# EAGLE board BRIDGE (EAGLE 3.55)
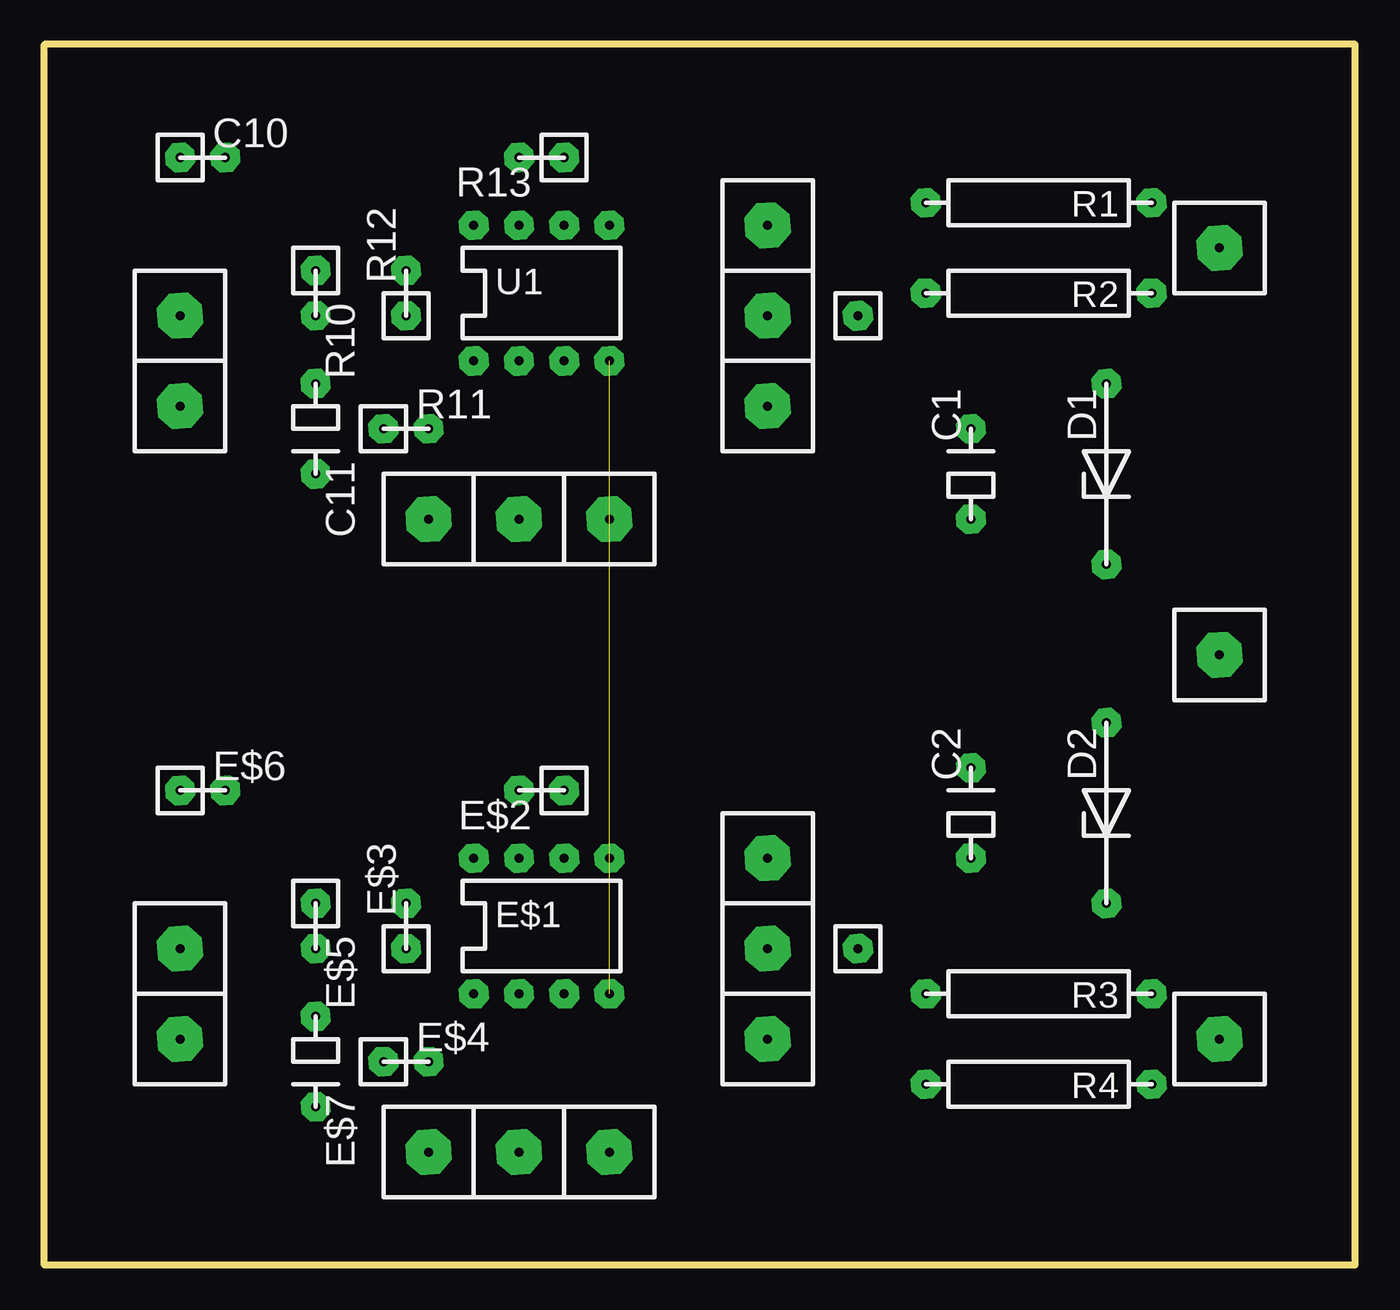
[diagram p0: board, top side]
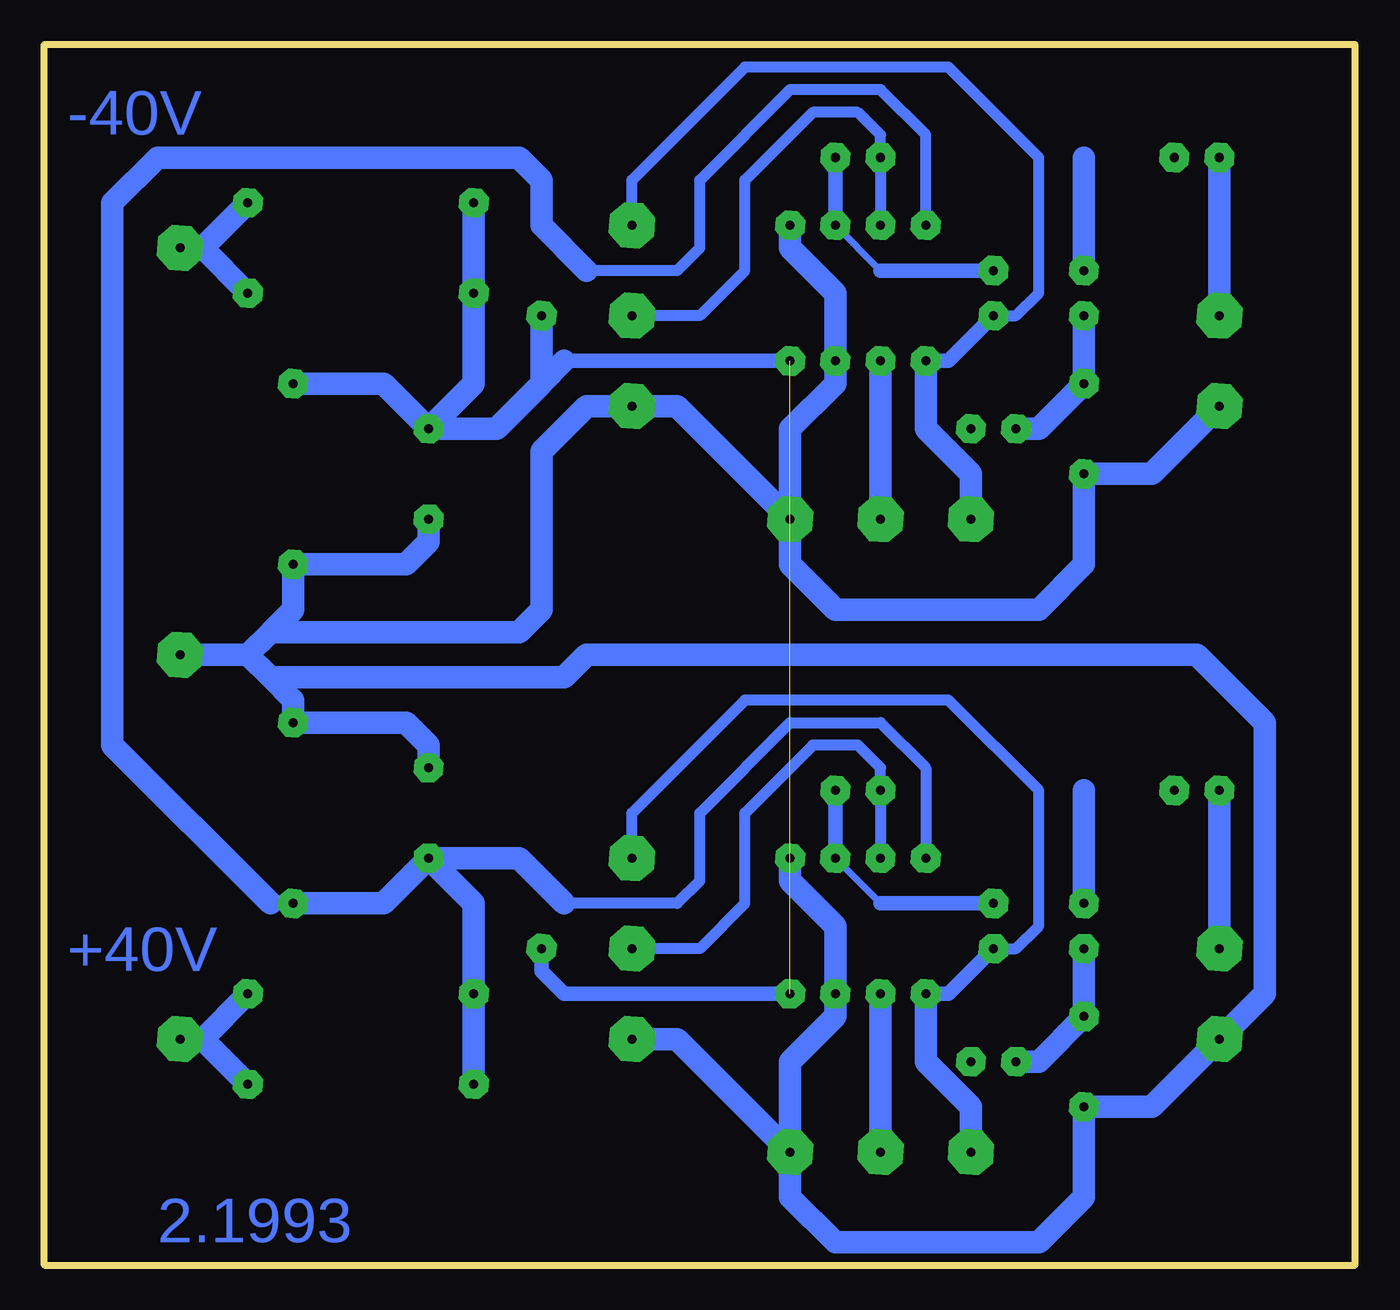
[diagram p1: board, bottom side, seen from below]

Size 73.66 x 68.58 mm. Coordinates in mm from the lower left corner, seen from the top.
Outline: 73.66,0 73.66,68.58 0,68.58 0,0 73.66,0
Copper layers used: Bottom

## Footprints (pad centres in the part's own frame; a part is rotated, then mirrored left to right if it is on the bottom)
 = drill 0.508 pad 1.651 octagon:  0,0;  5.08,0
,5 = drill 0.508 pad 1.651 octagon:  0,0;  2.54,0
10 = drill 0.508 pad 1.651 octagon:  0,0;  10.16,0
L8 = drill 0.508 pad 1.651 octagon:  0,0;  2.54,0;  5.08,0;  7.62,0;  7.62,7.62;  5.08,7.62;  2.54,7.62;  0,7.62
D = drill 0.508 pad 2.54 octagon:  2.54,2.54
D NORM = drill 0.508 pad 1.651 octagon:  1.27,1.27
2,5 = drill 0.508 pad 1.651 octagon:  0,0;  12.7,0

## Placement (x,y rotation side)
C1  []  52.07,41.91 90 top
C2  []  52.07,22.86 90 top
C10  [,5]  7.62,62.23 0 top
C11  []  15.24,49.53 270 top
D1  [10]  59.69,39.37 90 top
D2  [10]  59.69,20.32 90 top
E$1  [L8]  24.13,15.24 0 top
E$2  [,5]  29.21,26.67 180 top
E$3  [,5]  20.32,17.78 90 top
E$4  [,5]  19.05,11.43 0 top
E$5  [,5]  15.24,20.32 270 top
E$6  [,5]  7.62,26.67 0 top
E$7  []  15.24,13.97 270 top
E$8  [D]  5.08,15.24 0 top
E$9  [D]  5.08,10.16 0 top
E$10  [D]  24.13,3.81 0 top
E$11  [D]  29.21,3.81 0 top
E$12  [D]  19.05,3.81 0 top
E$13  [D]  38.1,20.32 0 top
E$14  [D]  38.1,15.24 0 top
E$15  [D]  38.1,10.16 0 top
E$16  [D NORM]  44.45,16.51 0 top
E$17  [D NORM]  44.45,52.07 0 top
R1  [2,5]  62.23,59.69 180 top
R2  [2,5]  62.23,54.61 180 top
R3  [2,5]  62.23,15.24 180 top
R4  [2,5]  62.23,10.16 180 top
R10  [,5]  15.24,55.88 270 top
R11  [,5]  19.05,46.99 0 top
R12  [,5]  20.32,53.34 90 top
R13  [,5]  29.21,62.23 180 top
U1  [L8]  24.13,50.8 0 top
X1  [D]  63.5,54.61 0 top
X2  [D]  63.5,31.75 0 top
X3  [D]  63.5,10.16 0 top
X10  [D]  5.08,50.8 0 top
X11  [D]  5.08,45.72 0 top
X12  [D]  24.13,39.37 0 top
X13  [D]  29.21,39.37 0 top
X14  [D]  19.05,39.37 0 top
X15  [D]  38.1,50.8 0 top
X16  [D]  38.1,45.72 0 top
X17  [D]  38.1,55.88 0 top

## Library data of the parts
C1 C2 C10 C11 D1 D2 E$1-E$7 R1-R4 R10-R13 U1 = PACKAGES
E$8-E$17 X1-X3 X10-X17 = VT

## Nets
+15V: C2. D2. E$1. R3. R4. U1.
-15V: C1. D1. E$1. E$16. E$17. R1. R2. U1.
GND: C1. C2. C11. D1. D2. E$1. E$7. E$9. E$11. E$15. U1. X2. X11. X13. X16.
N00001: R3. R4. X3.
N00002: R1. R2. X1.
N00003: R12. U1. X14. X17.
N00004: R12. R13. U1.
N00005: C10. X10.
N00006: C10. R10.
N00007: C11. R10. R11.
N00008: R11. U1. X12.
N00009: R13. U1. X15.
S$1: E$1. E$3. E$12. E$13.
S$2: E$1. E$2. E$3.
S$3: E$6. E$8.
S$4: E$5. E$6.
S$5: E$4. E$5. E$7.
S$6: E$1. E$4. E$10.
S$7: E$1. E$2. E$14.

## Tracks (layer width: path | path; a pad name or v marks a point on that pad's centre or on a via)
+15V
  Bottom 0.61: 44.45,20.32 38.1,20.32 36.83,21.59 36.83,25.4 31.75,30.48 26.67,30.48 24.13,27.94 E$1. | 43.18,55.88 38.1,55.88 36.83,57.15 36.83,60.96 31.75,66.04 26.67,66.04 24.13,63.5 U1.
  Bottom 0.813: 59.69,20.32 60.96,20.32
  Bottom 1.27: 43.18,55.88 45.72,58.42 45.72,60.96 46.99,62.23 67.31,62.23 69.85,59.69 69.85,29.21 60.96,20.32 | 59.69,20.32 54.61,20.32 52.07,22.86 | 52.07,22.86 49.53,20.32 R3. R4. | 44.45,20.32 46.99,22.86 52.07,22.86
-15V  (1 unrouted)
  Bottom 0.813: 31.75,15.24 44.45,15.24 45.72,16.51 E$16. | 31.75,50.8 44.45,50.8
  Bottom 1.27: E$17. 45.72,49.53 | 45.72,49.53 48.26,46.99 C1. | R1. R2. 49.53,49.53 C1. | C1. 54.61,49.53 D1. | 45.72,49.53 44.45,50.8
GND
  Bottom 1.27: E$11. 31.75,3.81 29.21,1.27 17.78,1.27 15.24,3.81 E$7. 11.43,8.89 E$9. 5.08,15.24 5.08,30.48 8.89,34.29 43.18,34.29 44.45,33.02 60.96,33.02 | E$11. 31.75,11.43 29.21,13.97 29.21,15.24 29.21,19.05 31.75,21.59 31.75,22.86 | E$11. 38.1,12.7 E$15. | X13. 31.75,39.37 29.21,36.83 17.78,36.83 15.24,39.37 C11. 11.43,44.45 X11. | X13. 31.75,46.99 29.21,49.53 29.21,50.8 29.21,54.61 31.75,57.15 31.75,58.42 | X13. 38.1,48.26 X16. 43.18,48.26 45.72,45.72 45.72,36.83 46.99,35.56 60.96,35.56 | 62.23,34.29 60.96,33.02 | 62.23,34.29 60.96,35.56 | 62.23,34.29 X2. | 52.07,41.91 52.07,40.64 53.34,39.37 59.69,39.37 59.69,36.83 60.96,35.56 | C2. 52.07,29.21 53.34,30.48 D2. 59.69,31.75 60.96,33.02
N00001
  Bottom 1.27: 62.23,15.24 64.77,12.7 | X3. 64.77,12.7 | 64.77,12.7 62.23,10.16
N00002
  Bottom 1.27: 62.23,54.61 64.77,57.15 | 64.77,57.15 X1. | 62.23,59.69 64.77,57.15
N00003
  Bottom 0.61: X17. 40.64,60.96 34.29,67.31 22.86,67.31 17.78,62.23 17.78,54.61 19.05,53.34 20.32,53.34
  Bottom 0.813: 24.13,50.8 22.86,50.8 20.32,53.34
  Bottom 1.27: 24.13,50.8 24.13,46.99 21.59,44.45 X14.
N00004
  Bottom 0.406: 26.67,55.88 29.21,58.42
  Bottom 0.813: R12. 26.67,55.88 | 29.21,62.23 29.21,58.42
N00005
  Bottom 1.27: X10. 7.62,62.23
N00006
  Bottom 1.27: 15.24,62.23 15.24,55.88
N00007
  Bottom 1.27: R10. 15.24,49.53 17.78,46.99 19.05,46.99
N00008
  Bottom 1.27: 26.67,50.8 26.67,46.99 X12.
N00009
  Bottom 0.61: 26.67,58.42 R13. 26.67,63.5 27.94,64.77 30.48,64.77 34.29,60.96 34.29,55.88 36.83,53.34 X15.
S$1
  Bottom 0.61: 20.32,17.78 19.05,17.78 17.78,19.05 17.78,26.67 22.86,31.75 34.29,31.75 40.64,25.4 E$13.
  Bottom 0.813: 24.13,13.97 24.13,15.24 22.86,15.24 20.32,17.78
  Bottom 1.27: E$12. 21.59,8.89 24.13,11.43 24.13,15.24
S$2
  Bottom 0.406: 26.67,20.32 29.21,22.86
  Bottom 0.813: E$3. 26.67,20.32 | 29.21,26.67 29.21,22.86
S$3
  Bottom 1.27: E$8. 7.62,26.67
S$4
  Bottom 1.27: 15.24,26.67 15.24,20.32
S$5
  Bottom 1.27: E$5. 15.24,13.97 17.78,11.43 19.05,11.43
S$6
  Bottom 1.27: 26.67,15.24 26.67,11.43 E$10.
S$7
  Bottom 0.61: 26.67,22.86 E$2. 26.67,27.94 27.94,29.21 30.48,29.21 34.29,25.4 34.29,20.32 36.83,17.78 E$14.

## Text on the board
Bottom: -40V | +40V | 2.1993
